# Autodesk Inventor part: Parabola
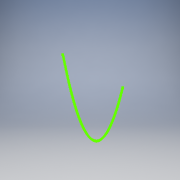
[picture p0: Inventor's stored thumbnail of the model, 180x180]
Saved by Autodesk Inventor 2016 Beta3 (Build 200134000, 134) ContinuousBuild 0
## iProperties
Created: 2008-02
Part Number: Parabola
Document SubType Name: Modeling
Designer: Autodesk, Inc.
Density: 1 g/cm^3
Material: Generic
Appearance: Default
Author: Autodesk, Inc.
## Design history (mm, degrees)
sketch "Sketch1"
  geometry: 300 further points
  constraints: 300 other
